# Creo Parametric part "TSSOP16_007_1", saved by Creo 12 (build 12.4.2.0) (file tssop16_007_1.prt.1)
Units: Custom; MM, KILOGRAM, SECS

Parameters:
  PTC_WM_ITERATION = "0"
  PTC_WM_VERSION = "-.0"
  PTC_WM_LIFECYCLE_STATE = "In Work"
  PTC_WM_LIFECYCLE = "MO_CADDocument"
  PTC_WM_CREATED_BY = "Maximilian Roepper (Z0017RMS: MO)"
  PTC_WM_CREATED_ON = "18-Sep-26 11:36:42 AM"
  PTC_WM_MODIFIED_BY = "Maximilian Roepper (Z0017RMS: MO)"
  PTC_WM_MODIFIED_ON = "18-Sep-26 11:36:46 AM"
  PDMLINKNUMBER = "PDM000071455226"
  PTC_WM_NAME = "tssop16_007_1.prt"
  PTC_WM_NUMBER = "PDM000071455226"

Other parameters: WEIGHT, WEIGHT_FACTOR, WEIGHT_ADD, _MASS_TEMP, _DIFF_TEMP, MC_ERRORS, SUPPLIER

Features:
  1. coordinate system
  2. datum plane "PRT_YZ"
  3. datum plane "PRT_XY"
  4. datum plane "PRT_XZ"
  5. coordinate system
  6. datum axis
  7. datum axis
  8. datum axis
  9. coordinate system
  10. imported feature

Other named items: PRT, SIEMENS_MO, DRW_VIEW_ORG, PRT_X, PRT_Y, PRT_Z, CS0, ROUGH_GROB

Layers: 00_STD_CSYS-KSYS, 01_STD_PLANES-EBENEN, 02_STD_AXES-ACHSEN, 03_STD_CSYS-KSYS, 24_IMPORT_FEAT-IMPORT_KE

Surfaces: 14 plane, 8 cylinder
